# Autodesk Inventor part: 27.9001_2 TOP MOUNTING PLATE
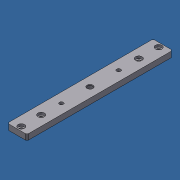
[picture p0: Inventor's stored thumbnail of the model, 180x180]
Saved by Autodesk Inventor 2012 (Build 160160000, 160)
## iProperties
Created: 2013-11
Part Number: 27.9001_2 TOP MOUNTING PLATE
Material: Aluminum-6061
Description: AL BARSTOCK 1/2" x 1.75"
Document SubType Name: Modeling
Designer: Admin
Stock Number: 20.9339 AL BARSTOCK 1/2" x 1.75"
Density: 2.71 g/cm^3
Author: Admin
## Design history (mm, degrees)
sketch "Sketch1"
  geometry: L1 (-22.225, -6.35)-(22.225, -6.35); L2 (22.225, -6.35)-(22.225, 6.35); L3 (22.225, 6.35)-(-22.225, 6.35); L4 (-22.225, 6.35)-(-22.225, -6.35); 3 further points
  constraints: 8 end point, 2 midpoint, 2 parallel, 1 horizontal, 1 horizontal alignment, 1 perpendicular, 1 vertical alignment
  dimensions: "d0" = 44.45 distance of L2.end L3.end; "d1" = 12.7 distance of L3.end L1.start
extrude "Extrusion2" new body sketch "Sketch1" stored distance "d4" = 330.2; taper "d5" = 0 deg
sketch "Sketch2"
  geometry: C1 r 6.744 at (22.225, -165.1); 1 further point
  constraints: 1 centre point, 1 coincident
  dimensions: "d6" = 13.4874 diameter of C1
extrude "Extrusion3" cut sketch "Sketch2" distance "d7" = 381; taper "d8" = 0 deg
sketch "Sketch3"
  geometry: C1 r 6.744 at (22.225, -165.1) reference; C2 r 10 at (22.225, -165.1)
  constraints: 1 centre point, 1 coincident
  dimensions: "d9" = 20 diameter of C2
extrude "Extrusion4" cut sketch "Sketch3" distance "d10" = 10.2108; taper "d11" = 0 deg
sketch "Sketch4"
  geometry: A1 r 3.824 centre (22.225, -100.1) between (19.975, -97.009) and (24.475, -97.009) reference; A2 r 3.824 centre (22.225, -230.1) between (24.475, -233.191) and (19.975, -233.191) reference; 2 further points
  constraints: 2 coincident
hole "Hole1" sketch "Sketch4" at (22.225, -230.1), (22.225, -100.1) diameter "d12" = 9; stored, may be unused: countersink angle "d16" = 82 deg, drill point angle "d18" = 118 deg; dims "d13" = 19.05, "d14" = 15, "d15" = 5.5, "d17" = 25.4
sketch "Sketch5"
  geometry: L1 (0, 0)-(44.45, 0) reference; L2 (44.45, 330.2)-(0, 330.2) reference; 7 further points
  constraints: 4 vertical alignment, 3 midpoint
  dimensions: "d19" = 9.5 distance from line of point (22.225, 9.5) L1; "d20" = 45 distance of point (22.225, 54.5) point (22.225, 9.5); "d21" = 9.5 distance from line of point (22.225, 320.7) L2 (= d19); "d22" = 45 distance of point (22.225, 275.7) point (22.225, 320.7) (= d20)
hole "Hole2" sketch "Sketch5" at (22.225, 9.5), (22.225, 54.5), (22.225, 275.7), (22.225, 320.7) diameter "d23" = 9; stored, may be unused: countersink angle "d27" = 82 deg, drill point angle "d29" = 118 deg; dims "d24" = 19.05, "d25" = 15, "d26" = 5.5, "d28" = 25.4
chamfer "Chamfer2" distance "d33" = 3.175; stored, may be unused: second distance "d34" = 3.175, angle "d35" = 45 deg
body "Solid1"
node "Reference1"
node "Reference2"
